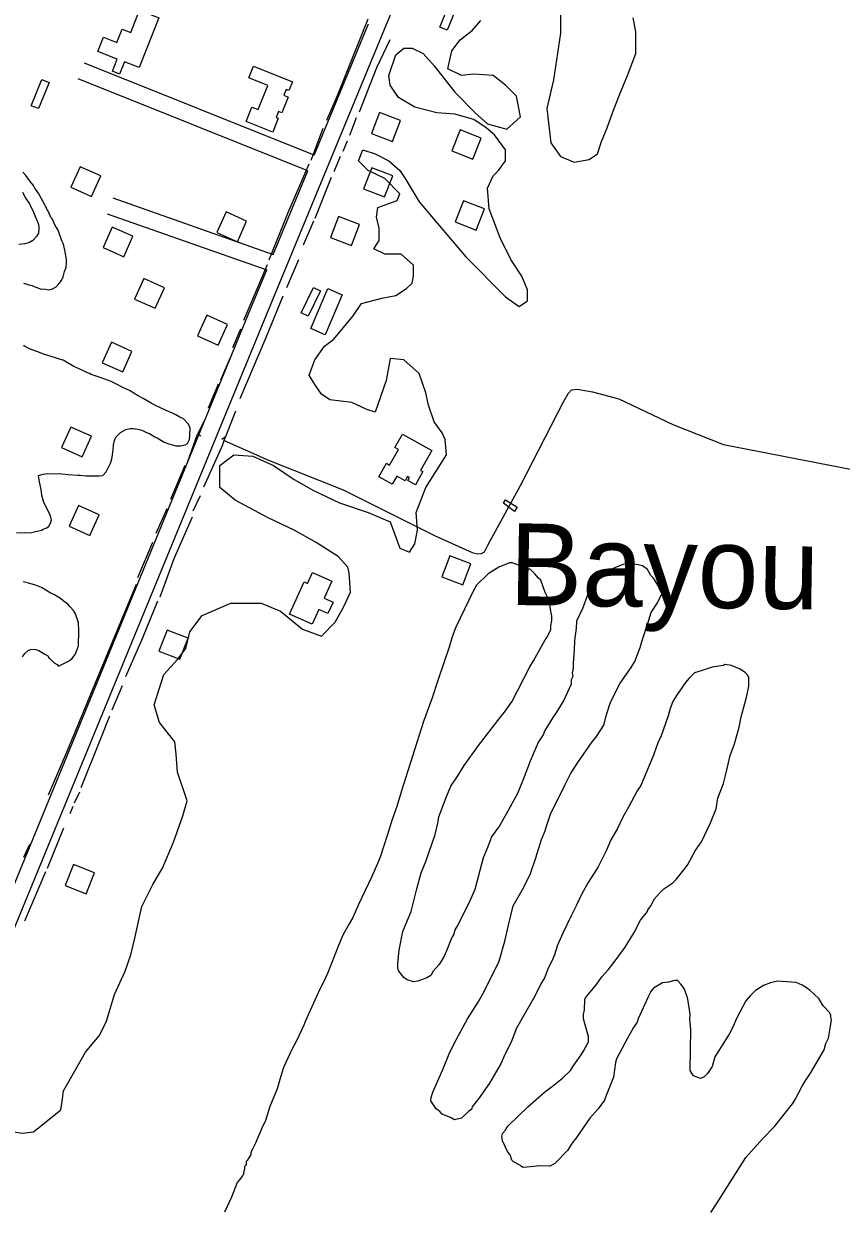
# Model space of a CAD drawing. Extents: x 3329297 to 3367176, y 649250 to 674653.
# Drawn here: x 3351319 to 3352769, y 657903 to 660007 of the extents above; entities that cross this region are included whole.
import ezdxf

# ---------------------------------------------------------------- set-up
doc = ezdxf.new("R2010")
doc.units = 0
for name, color, linetype in [('V-BLDG-OTLN', 7, 'Continuous'), ('V-BRDG-OTLN', 7, 'Continuous'), ('V-ROAD-CNTR', 7, 'Continuous'), ('V-SITE-VEGE', 7, 'Continuous'), ('V-TOPO-GNAM-IDEN', 7, 'Continuous'), ('V-TOPO-SHOR', 7, 'Continuous')]:
    doc.layers.add(name, color=color, linetype=linetype)

msp = doc.modelspace()

# ---------------------------------------------------------------- linework, layer by layer
at = {"layer": 'V-BLDG-OTLN'}
for points in [[(3351558.8, 660017.8), (3351523.7, 659929.7), (3351497.9, 659940), (3351489.1, 659918.1), (3351476.4, 659923.1), (3351485, 659944.7), (3351450.6, 659958.5), (3351460.7, 659983.8), (3351484.1, 659974.4), (3351493.5, 659997.9), (3351509, 659991.7), (3351524.8, 660031.4)], [(3352057.1, 660001.2), (3352076.1, 660047.4), (3352089.1, 660042.1), (3352070.1, 659995.9)], [(3351726.9, 659932.1), (3351795.9, 659904.6), (3351789.6, 659888.8), (3351784.5, 659890.9), (3351780.4, 659880.6), (3351788.1, 659877.5), (3351776.9, 659849.3), (3351770.9, 659851.6), (3351766.8, 659841.2), (3351770.7, 659839.7), (3351760.9, 659815.2), (3351713.6, 659834), (3351723.9, 659859.7), (3351734.8, 659855.3), (3351751.9, 659898), (3351718.6, 659911.3)], [(3351332.4, 659862.1), (3351351.1, 659908.5), (3351364.1, 659903.2), (3351345.4, 659856.9)], [(3351950.4, 659850.2), (3351935.9, 659812.9), (3351973.1, 659798.4), (3351987.7, 659835.6)], [(3352093.2, 659819), (3352078.7, 659781.8), (3352116, 659767.2), (3352130.5, 659804.5)], [(3351439.4, 659701), (3351455.7, 659737.5), (3351419.2, 659753.9), (3351402.9, 659717.4)], [(3351936.4, 659752), (3351921.9, 659714.8), (3351959.1, 659700.2), (3351973.7, 659737.5)], [(3351698.3, 659620.9), (3351714.6, 659657.4), (3351678.1, 659673.7), (3351661.8, 659637.2)], [(3352099, 659693.4), (3352084.5, 659656.1), (3352121.8, 659641.6), (3352136.3, 659678.9)], [(3351877.8, 659665.8), (3351863.2, 659628.5), (3351900.5, 659614), (3351915, 659651.2)], [(3351496.5, 659594.1), (3351512.8, 659630.6), (3351476.3, 659646.9), (3351460, 659610.4)], [(3351552.3, 659502.8), (3351568.7, 659539.3), (3351532.1, 659555.6), (3351515.8, 659519.1)], [(3351845.8, 659533.6), (3351824, 659488.5), (3351811.4, 659494.6), (3351833.1, 659539.7)], [(3351828.4, 659466.7), (3351858.8, 659537.6), (3351884, 659526.8), (3351853.6, 659455.9)], [(3351664.1, 659437.5), (3351680.4, 659474), (3351643.9, 659490.4), (3351627.6, 659453.9)], [(3351494.8, 659389.8), (3351511.1, 659426.3), (3351474.6, 659442.7), (3351458.3, 659406.2)], [(3351422.8, 659239.3), (3351439.2, 659275.8), (3351402.6, 659292.1), (3351386.3, 659255.6)], [(3351968.2, 659224.6), (3351983.7, 659252.2), (3351977.5, 659255.7), (3351991, 659279.7), (3352043, 659250.6), (3352023.2, 659215.2), (3352027.1, 659213), (3352014.1, 659189.8), (3352000.5, 659197.4), (3352003.4, 659202.6), (3352000, 659204.5), (3351995.5, 659196.5), (3351980.7, 659204.9), (3351972.7, 659190.7), (3351949.1, 659204), (3351962.5, 659227.8)], [(3351436.4, 659099.9), (3351452.8, 659136.4), (3351416.2, 659152.7), (3351399.9, 659116.2)], [(3352075.2, 659063.9), (3352060.7, 659026.7), (3352097.9, 659012.1), (3352112.5, 659049.4)], [(3351790.8, 658960), (3351816.4, 659017.3), (3351822.7, 659014.5), (3351831.4, 659034), (3351865.6, 659018.7), (3351852, 658988.3), (3351867.8, 658981.2), (3351858.8, 658961.1), (3351842.5, 658968.4), (3351830.8, 658942.2)], [(3351573.5, 658932), (3351559, 658894.8), (3351596.2, 658880.2), (3351610.8, 658917.5)], [(3351407.2, 658516), (3351392.7, 658478.7), (3351430, 658464.2), (3351444.5, 658501.5)]]:
    msp.add_lwpolyline(points, close=True, dxfattribs=at)
at = {"layer": 'V-BRDG-OTLN'}
msp.add_lwpolyline([(3352170.2, 659157), (3352174, 659163), (3352194.3, 659149.8), (3352189.6, 659142.3)], close=True, dxfattribs=at)
at = {"layer": 'V-ROAD-CNTR'}
for points in [[(3349953.5, 655116), (3350526.4, 656517.7), (3351118.5, 657956.3), (3351749.9, 659491.3), (3351987.7, 660066.8)], [(3351834.3, 659774.3), (3351930.7, 660007.5)], [(3351834.3, 659774.3), (3351426.9, 659937.6)], [(3351822.9, 659746.6), (3351415.7, 659909.8)], [(3351761.7, 659598.4), (3351822.9, 659746.6)], [(3351477.2, 659698.4), (3351761.7, 659598.4)], [(3351467.2, 659670.1), (3351750.2, 659570.7)], [(3351232.2, 658311.6), (3351722.1, 659502.8), (3351750.2, 659570.7)]]:
    msp.add_lwpolyline(points, dxfattribs=at)
at = {"layer": 'V-SITE-VEGE'}
for points in [[(3352271.1, 660098.2), (3352271.1, 659991), (3352258.9, 659908.2), (3352246.8, 659857), (3352254.1, 659796.1), (3352271.1, 659771.8), (3352295.5, 659762), (3352322.2, 659766.9), (3352336.9, 659776.6), (3352344.2, 659798.6), (3352353.9, 659822.9), (3352363.6, 659849.7), (3352375.8, 659881.4), (3352390.4, 659915.5), (3352405, 659954.5), (3352405, 659993.5), (3352400.2, 660017.8)], [(3351996, 659732.8), (3352020.4, 659691.4), (3352049.6, 659657.2), (3352103.1, 659593.9), (3352173.7, 659523.2), (3352198.1, 659506.2), (3352212.7, 659515.9), (3352212.7, 659535.4), (3352203, 659559.8), (3352183.5, 659589), (3352164, 659628), (3352144.5, 659679.2), (3352142.1, 659715.7), (3352151.8, 659737.6), (3352161.6, 659747.4), (3352173.7, 659764.4), (3352173.7, 659783.9), (3352154.3, 659810.7), (3352139.6, 659822.9), (3352117.7, 659837.5), (3352083.7, 659847.3), (3352052, 659849.7), (3352013.1, 659859.5), (3351983.8, 659876.5), (3351969.2, 659898.5), (3351966.8, 659915.5), (3351979, 659952.1), (3351993.6, 659964.2), (3352008.2, 659964.2), (3352027.7, 659954.5), (3352047.1, 659932.6), (3352083.7, 659886.3), (3352120.2, 659849.7), (3352142.1, 659830.2), (3352176.2, 659820.5), (3352200.5, 659842.4), (3352193.2, 659879), (3352173.7, 659898.5), (3352151.8, 659915.5), (3352117.7, 659917.9), (3352095.8, 659915.5), (3352071.5, 659927.7), (3352078.8, 659959.4), (3352093.4, 659978.9), (3352115.3, 659995.9), (3352129.9, 660013)], [(3351389.8, 658115), (3351428.7, 658183.2), (3351453.1, 658212.4), (3351465.3, 658236.8), (3351479.9, 658285.5), (3351499.3, 658326.9), (3351509.1, 658356.2), (3351516.4, 658385.4), (3351528.6, 658441.5), (3351548, 658480.4), (3351565.1, 658509.7), (3351584.6, 658556), (3351601.6, 658602.3), (3351608.9, 658629.1), (3351591.9, 658680.2), (3351589.4, 658711.9), (3351587, 658733.8), (3351560.2, 658767.9), (3351550.5, 658799.6), (3351567.5, 658853.2), (3351591.9, 658880), (3351606.5, 658899.5), (3351613.8, 658928.7), (3351635.7, 658958), (3351686.8, 658979.9), (3351740.4, 658979.9), (3351774.5, 658965.3), (3351813.4, 658933.6), (3351847.5, 658921.4), (3351871.8, 658945.8), (3351886.5, 658972.6), (3351898.6, 658999.4), (3351896.2, 659033.5), (3351893.8, 659043.3), (3351876.7, 659062.7), (3351837.8, 659087.1), (3351798.8, 659109), (3351752.5, 659131), (3351694.1, 659162.6), (3351667.3, 659184.6), (3351667.3, 659223.6), (3351691.7, 659243), (3351725.8, 659240.6), (3351762.3, 659223.6), (3351798.8, 659199.2), (3351832.9, 659179.7), (3351879.1, 659157.8), (3351930.3, 659140.7), (3351969.2, 659123.7), (3351986.3, 659077.4), (3352003.3, 659070.1), (3352013.1, 659084.7), (3352017.9, 659109), (3352015.5, 659140.7), (3352032.5, 659184.6), (3352069, 659243), (3352066.6, 659269.8), (3352061.7, 659282), (3352047.1, 659301.5), (3352037.4, 659330.8), (3352032.5, 659352.7), (3352020.4, 659386.8), (3351993.6, 659411.2), (3351969.2, 659413.6), (3351961.9, 659374.6), (3351942.4, 659318.6), (3351927.8, 659323.5), (3351901.1, 659335.6), (3351862.1, 659340.5), (3351847.5, 659350.3), (3351835.3, 659367.3), (3351825.6, 659384.4), (3351835.3, 659411.2), (3351852.4, 659435.5), (3351869.4, 659447.7), (3351903.5, 659489.1), (3351918.1, 659511.1), (3351954.6, 659520.8), (3351979, 659525.7), (3351998.4, 659537.9), (3352008.2, 659547.6), (3352010.6, 659559.8), (3352010.6, 659579.3), (3351988.7, 659598.8), (3351959.5, 659598.8), (3351940, 659608.5), (3351949.8, 659623.1), (3351949.8, 659645.1), (3351944.9, 659664.6), (3351947.3, 659681.6), (3351966.8, 659688.9), (3351981.4, 659693.8), (3351986.3, 659706), (3351959.5, 659732.8), (3351930.3, 659747.4), (3351913.2, 659764.4), (3351920.5, 659783.9), (3351942.4, 659776.6), (3351966.8, 659764.4), (3351986.3, 659747.4), (3351996, 659732.8)], [(3351318.5, 659547.6), (3351324.7, 659545.8), (3351328.1, 659544.1), (3351334.3, 659542.9), (3351338.8, 659541.1), (3351344.4, 659539.3), (3351348.4, 659537.5), (3351358, 659536.8), (3351363.1, 659535.6), (3351368.8, 659536.7), (3351371.6, 659537.8), (3351376.7, 659541.1), (3351381.4, 659546.1), (3351386, 659552.3), (3351388.9, 659558.4), (3351391.3, 659568), (3351394.3, 659575.3), (3351395, 659584.4), (3351395, 659589.5), (3351393.5, 659599.1), (3351391.9, 659606), (3351389.8, 659616.2), (3351387, 659622.5), (3351380, 659641.2), (3351375, 659649.3), (3351372.8, 659654.9), (3351369, 659662.4), (3351366.7, 659665.2), (3351365.1, 659670.4), (3351363.5, 659672.1), (3351361.8, 659676.1), (3351360.1, 659678.4), (3351359.1, 659682.3), (3351358, 659684.1), (3351356.3, 659686.3), (3351350.3, 659697.8), (3351345.8, 659705.8), (3351342.5, 659710.9), (3351339.2, 659714.9), (3351336.4, 659720.6), (3351331.4, 659726.9), (3351323.1, 659738.4), (3351317.5, 659744.1)], [(3351317, 659708.5), (3351323.1, 659697.6), (3351329.1, 659687.9), (3351336.3, 659673.1), (3351340.1, 659664.5), (3351343.9, 659654.8), (3351345.6, 659651.4), (3351346.1, 659646.3), (3351346, 659643.5), (3351345.4, 659636.1), (3351341.9, 659629.9), (3351335.5, 659622.7), (3351329.2, 659619.4), (3351321.3, 659617.2), (3351310.5, 659615.7)], [(3351306.1, 659104.5), (3351319.7, 659104.8), (3351330.5, 659104.7), (3351337.9, 659106.2), (3351350.4, 659109.4), (3351353.8, 659111.1), (3351360.1, 659113.3), (3351363.5, 659116), (3351366.4, 659121.7), (3351368.2, 659127.3), (3351366.6, 659134.7), (3351358.9, 659150.7), (3351355.1, 659158.1), (3351351.3, 659171.2), (3351349.8, 659181.4), (3351347.2, 659195), (3351346.1, 659201.2), (3351345.6, 659206.3), (3351353.6, 659208.5), (3351361, 659209.5), (3351387, 659209.1), (3351397.7, 659207.8), (3351415.3, 659207), (3351419.2, 659206.9), (3351429.4, 659205.6), (3351453.8, 659205.3), (3351459.4, 659206.3), (3351465.2, 659212.5), (3351473.9, 659229.3), (3351475.8, 659237.8), (3351477.7, 659252.5), (3351478.4, 659260.4), (3351480.2, 659268.3), (3351482.5, 659273.9), (3351487.7, 659279.5), (3351490.6, 659282.3), (3351500.3, 659287.8), (3351507.7, 659289.4), (3351513.4, 659289.3), (3351521.3, 659288.6), (3351528.6, 659286.8), (3351537, 659282.7), (3351542.1, 659280.4), (3351551.6, 659274.6), (3351555.6, 659272.8), (3351568.5, 659265.2), (3351576.4, 659262.3), (3351588.8, 659258.7), (3351597.3, 659258.6), (3351605.8, 659260.7), (3351609.8, 659262.9), (3351613.3, 659270.2), (3351614, 659277.6), (3351614.2, 659290), (3351611.4, 659297.4), (3351602.5, 659306.6), (3351596.3, 659309.6), (3351589, 659313.6), (3351582.8, 659316.6), (3351571.6, 659321.3), (3351560.3, 659326.5), (3351553.1, 659330.6), (3351545.2, 659334.7), (3351531.2, 659342.8), (3351522.2, 659347.5), (3351507, 659356.8), (3351496.3, 659361.5), (3351482.3, 659368.5), (3351474.4, 659372.6), (3351454.7, 659380.2), (3351438.9, 659385.6), (3351435.6, 659387.3), (3351431.1, 659389.1), (3351418.7, 659394.9), (3351408, 659399.6), (3351392.3, 659408.9), (3351388.9, 659410.7), (3351386.1, 659411.3), (3351375.4, 659414.8), (3351354, 659421.4), (3351344.4, 659425.5), (3351332.6, 659429.6), (3351328.1, 659431.4), (3351320.8, 659435.5), (3351319.1, 659437.2)], [(3352045.1, 658326.2), (3352041.9, 658320), (3352040.3, 658318.5), (3352034, 658315.4), (3352018.3, 658309.4), (3352010.5, 658308), (3351999.6, 658311.3), (3351993.5, 658316), (3351984.3, 658327.1), (3351982.8, 658331.8), (3351982.9, 658341.2), (3351984.9, 658364.5), (3351991.6, 658397.2), (3351999.7, 658417.4), (3352006.2, 658432.9), (3352016.2, 658473.3), (3352024.4, 658501.2), (3352032.5, 658521.4), (3352048.8, 658569.5), (3352053.8, 658589.7), (3352055.5, 658600.6), (3352058.8, 658610), (3352068.5, 658634.8), (3352076.6, 658654.9), (3352087.8, 658671.9), (3352100.6, 658692), (3352126.1, 658727.5), (3352164.3, 658776.9), (3352172.2, 658786.1), (3352185, 658804.6), (3352217.2, 658866.6), (3352223.6, 658877.4), (3352244.4, 658914.5), (3352247.6, 658919.2), (3352254.1, 658933.1), (3352254.2, 658939.3), (3352255.9, 658948.7), (3352256, 658956.5), (3352253.1, 658972.1), (3352253.2, 658976.8), (3352248.7, 658989.4), (3352244.1, 658998.8), (3352236.7, 659020.7), (3352232, 659023.9), (3352225.9, 659031.8), (3352218.2, 659039.7), (3352185.6, 659051.2), (3352181, 659051.2), (3352162.1, 659043.7), (3352143.2, 659031.5), (3352122.6, 659011.6), (3352116.2, 659000.7), (3352085.6, 658937.2), (3352079.1, 658920.2), (3352074.1, 658901.5), (3352054.5, 658844.1), (3352043.1, 658809.9), (3352028.5, 658769.6), (3351989.1, 658646.9), (3351980.9, 658618.9), (3351972.8, 658595.7), (3351964.6, 658569.3), (3351951.5, 658528.9), (3351946.6, 658518), (3351936.9, 658494.8), (3351912.7, 658445.2), (3351903, 658422), (3351896.6, 658411.1), (3351885.4, 658391), (3351877.3, 658372.4), (3351857.8, 658322.8), (3351854.6, 658315), (3351841.7, 658288.7), (3351819.1, 658239.1), (3351815.9, 658231.4), (3351803, 658203.5), (3351794.9, 658188), (3351780.4, 658157), (3351778.8, 658152.3), (3351772.2, 658130.6), (3351768.9, 658118.2), (3351756, 658087.2), (3351747.8, 658062.3), (3351741.3, 658048.4), (3351730, 658022), (3351725.2, 658011.2), (3351723.6, 658009.6), (3351721.9, 658005), (3351721.9, 658001.9), (3351718.7, 657995.7), (3351715.5, 657991), (3351713.9, 657989.5), (3351713.8, 657983.3), (3351710.6, 657980.2), (3351710.6, 657975.5), (3351708.9, 657969.3), (3351708.9, 657966.2), (3351707.3, 657964.6), (3351705.7, 657961.5), (3351704.1, 657960), (3351697.7, 657952.3)], [(3352122.8, 658097.2), (3352114.8, 658086.4), (3352113.2, 658081.7), (3352108.5, 658078.7), (3352095.8, 658066.4), (3352083.3, 658063.5), (3352077.1, 658066.7), (3352061.6, 658073.2), (3352057, 658077.9), (3352050.8, 658082.7), (3352041.6, 658096.9), (3352041.7, 658103.1), (3352045, 658112.4), (3352062.8, 658152.7), (3352074.1, 658180.6), (3352082.2, 658197.7), (3352106.3, 658242.6), (3352125.4, 658271.9), (3352136.7, 658292), (3352162.4, 658344.7), (3352172.3, 658380.4), (3352179, 658408.4), (3352187.3, 658442.6), (3352203.3, 658470.4), (3352217.8, 658498.3), (3352227.6, 658527.8), (3352237.5, 658560.4), (3352244, 658575.9), (3352245.6, 658582.2), (3352253.8, 658605.4), (3352279.5, 658658.1), (3352289.2, 658676.7), (3352302, 658696.8), (3352327.5, 658733.8), (3352333.9, 658741.5), (3352348.2, 658763.2), (3352353.2, 658781.8), (3352358.1, 658798.9), (3352361.4, 658806.6), (3352377.4, 658837.6), (3352396.6, 658865.4), (3352403, 658876.2), (3352412.7, 658901), (3352416, 658913.5), (3352427.5, 658947.6), (3352432.4, 658963.2), (3352443.6, 658980.2), (3352451.6, 658997.2), (3352450.1, 658998.8), (3352444, 659011.4), (3352439.5, 659019.2), (3352436.4, 659024), (3352431.8, 659028.7), (3352425.8, 659039.7), (3352416.5, 659046.1), (3352408.7, 659047.8), (3352399.4, 659049.5), (3352382.2, 659048.2), (3352360.2, 659039.2), (3352352.4, 659036.2), (3352336.5, 659020.8), (3352322.2, 659000.7), (3352318.9, 658993), (3352310.8, 658971.2), (3352299.5, 658948), (3352299.3, 658935.5), (3352295.9, 658913.7), (3352295.6, 658896.6), (3352293.7, 658873.2), (3352293.6, 658863.8), (3352291.9, 658856.1), (3352293.4, 658849.8), (3352290.1, 658843.6), (3352290, 658835.8), (3352277.1, 658807.9), (3352272.3, 658800.2), (3352264.3, 658786.3), (3352257.9, 658777), (3352243.5, 658753.8), (3352240.3, 658746.1), (3352232.3, 658733.7), (3352224.2, 658715.1), (3352217.7, 658699.6), (3352204.8, 658667), (3352195, 658642.2), (3352175.8, 658606.6), (3352163, 658585), (3352148.6, 658564.9), (3352147, 658560.2), (3352140.5, 658543.2), (3352134, 658527.7), (3352119.1, 658471.7), (3352109.4, 658448.5), (3352088.5, 658408.2), (3352083.7, 658400.5), (3352082, 658392.7), (3352078.8, 658386.5), (3352069.1, 658363.3), (3352064.2, 658352.4), (3352056.2, 658338.5), (3352045.1, 658326.2)], [(3351317, 658884.6), (3351321, 658890.2), (3351327.3, 658895.8), (3351331.3, 658897.4), (3351337.5, 658897.9), (3351340.9, 658897.8), (3351346, 658895.5), (3351356.7, 658889.1), (3351361.7, 658886.2), (3351364.5, 658882.2), (3351366.2, 658881), (3351369, 658878.1), (3351373.4, 658874.1), (3351378.5, 658871.2), (3351380.7, 658867.8), (3351398.4, 658877.1), (3351404.7, 658881), (3351410.5, 658888.8), (3351412.8, 658894.5), (3351416.3, 658904), (3351416.7, 658930.6), (3351416.4, 658944.8), (3351413.7, 658952.2), (3351411, 658960.7), (3351407.7, 658966.5), (3351401.5, 658973.3), (3351397.6, 658977.9), (3351389.2, 658983.7), (3351384.2, 658987.8), (3351373.5, 658994.2), (3351366.2, 658998.2), (3351350.5, 659007.5), (3351344.9, 659009.9), (3351338.1, 659012.2), (3351327.4, 659015.2), (3351318.4, 659017.6)], [(3352168.7, 658038.8), (3352173.5, 658044.9), (3352175.1, 658048), (3352178.3, 658052.7), (3352213.1, 658086.5), (3352243.2, 658112.5), (3352257.4, 658123.2), (3352274.7, 658137), (3352289, 658150.8), (3352293.8, 658158.6), (3352308.1, 658178.6), (3352312.9, 658186.4), (3352321, 658201.8), (3352321.1, 658211.2), (3352315.2, 658231.6), (3352312.2, 658242.5), (3352312.4, 658250.3), (3352314, 658258.1), (3352314.3, 658276.8), (3352315.9, 658279.9), (3352320.7, 658286.1), (3352335, 658303.1), (3352344.6, 658317), (3352355.7, 658329.3), (3352370, 658347.8), (3352385.9, 658369.4), (3352395.5, 658384.8), (3352401.9, 658395.7), (3352413.2, 658417.3), (3352425.9, 658432.7), (3352426, 658435.9), (3352432.3, 658443.6), (3352437.2, 658454.4), (3352448.3, 658466.7), (3352454.6, 658472.9), (3352470.4, 658483.6), (3352476.7, 658489.7), (3352492.6, 658509.7), (3352497.4, 658515.9), (3352510.2, 658540.7), (3352521.4, 658556.1), (3352537.5, 658590.2), (3352547.3, 658615), (3352550.7, 658633.7), (3352560.4, 658660.1), (3352565.4, 658678.7), (3352572.1, 658709.8), (3352580.2, 658730), (3352588.5, 658759.5), (3352591.9, 658778.2), (3352598.5, 658801.5), (3352601.8, 658815.5), (3352605.2, 658832.6), (3352605.4, 658848.2), (3352602.4, 658852.9), (3352599.3, 658856.1), (3352590, 658862.5), (3352574.5, 658868.9), (3352563.6, 658870.7), (3352560.5, 658869.2), (3352540.1, 658866.3), (3352522.9, 658860.4), (3352508.8, 658855.9), (3352499.3, 658846.7), (3352492.9, 658839), (3352477, 658815.8), (3352470.6, 658805), (3352465.7, 658792.6), (3352462.4, 658780.1), (3352449.3, 658742.9), (3352444.5, 658733.6), (3352436.4, 658710.3), (3352413.7, 658656.1), (3352407.3, 658646.8), (3352392.8, 658618.9), (3352381.6, 658600.4), (3352371.9, 658578.7), (3352360.7, 658560.1), (3352352.7, 658541.5), (3352338.2, 658512.1), (3352320.6, 658484.3), (3352309.4, 658464.2), (3352299.7, 658444), (3352290, 658425.4), (3352275.5, 658394.5), (3352265.8, 658372.8), (3352260.9, 658355.7), (3352256.1, 658344.8), (3352249.6, 658332.4), (3352243.1, 658315.4), (3352236.7, 658304.5), (3352225.5, 658282.9), (3352203, 658242.6), (3352193.4, 658225.6), (3352183.7, 658200.8), (3352172.4, 658179.1), (3352165.9, 658163.6), (3352157.9, 658149.7), (3352145.1, 658128.1), (3352126, 658100.3), (3352122.8, 658097.2)], [(3352538, 657899), (3352549.1, 657916), (3352600.3, 657996.3), (3352630.4, 658030.2), (3352651.1, 658051.7), (3352682.9, 658091.8), (3352687.7, 658099.5), (3352700.5, 658124.3), (3352705.3, 658132), (3352714.9, 658145.9), (3352738.9, 658187.7), (3352742.2, 658198.6), (3352747, 658207.9), (3352750.5, 658229.7), (3352752.2, 658240.6), (3352750.7, 658245.3), (3352750.8, 658248.4), (3352749.3, 658253.1), (3352737, 658265.7), (3352729.4, 658278.3), (3352714, 658292.6), (3352707.8, 658297.4), (3352700.1, 658302.2), (3352689.3, 658307), (3352656.5, 658309.1), (3352648.7, 658307.7), (3352644, 658306.2), (3352631.4, 658301.7), (3352617.3, 658292.5), (3352614.1, 658289.5), (3352607.8, 658283.3), (3352599.8, 658274.1), (3352583.7, 658243.1), (3352577.3, 658227.6), (3352570.8, 658215.2), (3352545.3, 658175), (3352540.3, 658158), (3352532.3, 658145.6), (3352526, 658139.4), (3352519.7, 658136.4), (3352507.3, 658141.3), (3352505.8, 658142.9), (3352501.2, 658150.7), (3352502.3, 658224.1), (3352501, 658241.2), (3352501.2, 658250.6), (3352496.9, 658277.2), (3352495.4, 658283.5), (3352490.9, 658296), (3352484.8, 658303.9), (3352478.7, 658310.2), (3352474, 658310.3), (3352463, 658307.4), (3352452.1, 658306), (3352436.3, 658296.8), (3352431.6, 658290.7), (3352426.7, 658281.4), (3352409, 658242.6), (3352407.3, 658236.4), (3352400.9, 658227.2), (3352389.7, 658207), (3352370.5, 658171.5), (3352368.8, 658165.2), (3352365.3, 658138.8), (3352352.3, 658106.2), (3352349.1, 658098.4), (3352337.9, 658083), (3352323.6, 658066.1), (3352299.7, 658032.1), (3352296.5, 658027.5), (3352294.9, 658025.9), (3352288.5, 658016.7), (3352283.7, 658008.9), (3352275.8, 658001.2), (3352271, 657995.1), (3352261.5, 657985.9), (3352252.1, 657981.3), (3352234.9, 657981.6), (3352224, 657980.2), (3352205.3, 657978.9), (3352202.2, 657980.5), (3352200.6, 657982.1), (3352188.2, 657988.5), (3352185.2, 657991.7), (3352182.2, 658001.1), (3352177.6, 658005.9), (3352168.5, 658026.3), (3352167.1, 658034.1), (3352168.7, 658038.8)], [(3351187.7, 657885.9), (3351187.7, 657927.4), (3351195, 657951.7), (3351207.2, 657973.7), (3351224.2, 658022.4), (3351255.9, 658051.6), (3351285.1, 658044.3), (3351316.8, 658039.4), (3351336.2, 658041.9), (3351384.9, 658080.9), (3351387.4, 658095.5), (3351389.8, 658115)], [(3351697.7, 657952.3), (3351688, 657925.9), (3351675.1, 657899.6)]]:
    msp.add_lwpolyline(points, dxfattribs=at)
at = {"layer": 'V-TOPO-SHOR'}
for p, q in [((3351850, 659821.6), (3351828.7, 659765.1)), ((3351908.6, 659840.4), (3351896.8, 659809.5)), ((3351892.8, 659799), (3351885, 659780.9)), ((3351880.3, 659771.9), (3351869.3, 659744.8)), ((3351864.6, 659735), (3351835.4, 659662)), ((3351833.1, 659657.5), (3351815, 659614.6)), ((3351750.9, 659579.9), (3351709.2, 659481.3)), ((3351806.3, 659588.9), (3351785.1, 659539.3)), ((3351703.7, 659465.5), (3351689.5, 659432.4)), ((3351684.7, 659413.5), (3351668.2, 659375.2)), ((3351664.3, 659368.4), (3351646.3, 659325.5)), ((3351610.4, 659231.2), (3351627.4, 659279.6)), ((3351579.9, 659164.3), (3351605.8, 659224.5)), ((3351620, 659143.3), (3351632.5, 659170.4)), ((3351554, 659104.1), (3351573.6, 659147.7)), ((3351521.7, 659025), (3351548.4, 659088.2)), ((3351476, 658790.3), (3351494.1, 658833.9)), ((3351409.2, 658625.4), (3351418.5, 658645)), ((3351401.3, 658606.6), (3351406.8, 658619.4)), ((3351361.2, 658509.5), (3351390.3, 658581)), ((3351319.5, 658528.9), (3351329.7, 658552.2)), ((3351321.1, 658416.2), (3351358.1, 658503.5))]:
    msp.add_line(p, q, dxfattribs=at)
for points in [[(3352560.4, 659261.1), (3353184.4, 659140.1), (3354146.9, 659103.4), (3354676.3, 659123.6), (3356675.4, 660657.8), (3357924.8, 661661.2)], [(3351929.4, 660015.8), (3351875.1, 659879.5), (3351856.3, 659835.9)], [(3351968.3, 659978.9), (3351944.8, 659929.2), (3351914, 659850.9)], [(3351824.8, 659758.3), (3351787.9, 659671.8), (3351754, 659588.2)], [(3351778.8, 659524.2), (3351748.1, 659448.9), (3351702.6, 659342.1)], [(3351675, 659268.5), (3351753.3, 659233.2), (3351885.8, 659180.5), (3352048.9, 659099.2), (3352114.4, 659069.4), (3352124.9, 659067), (3352131, 659067.7), (3352136.3, 659070.6), (3352142.6, 659082.6), (3352200.2, 659188.6), (3352276.7, 659336.6), (3352285.3, 659352.4), (3352290.7, 659358.4), (3352300.6, 659359), (3352327.8, 659354.8), (3352374.5, 659342), (3352470.8, 659296.6), (3352560.4, 659261.1)], [(3351694.7, 659320.2), (3351677.3, 659275), (3351670.4, 659269.8)], [(3351642.2, 659308.9), (3351627.4, 659279.6), (3351633.4, 659276.5)], [(3351638.8, 659186.2), (3351671.8, 659259.2), (3351675, 659268.5), (3351677.3, 659275)], [(3351560.9, 658991.2), (3351586.2, 659059), (3351618.3, 659132.8)], [(3351362.9, 658639.6), (3351396.6, 658718.6), (3351446.2, 658838.3), (3351519.3, 659013.7)], [(3351500.4, 658849.7), (3351531, 658919.7), (3351557, 658983.7)], [(3351420.9, 658652.5), (3351454.8, 658736.8), (3351472.1, 658779.7)]]:
    msp.add_lwpolyline(points, dxfattribs=at)

# ---------------------------------------------------------------- texts
at = {"layer": 'V-TOPO-GNAM-IDEN'}
msp.add_text('Bayou Paul', height=145, rotation=359.1629, dxfattribs=at).set_placement((3352179.7, 658976.6))

doc.saveas('drawing.dxf')
